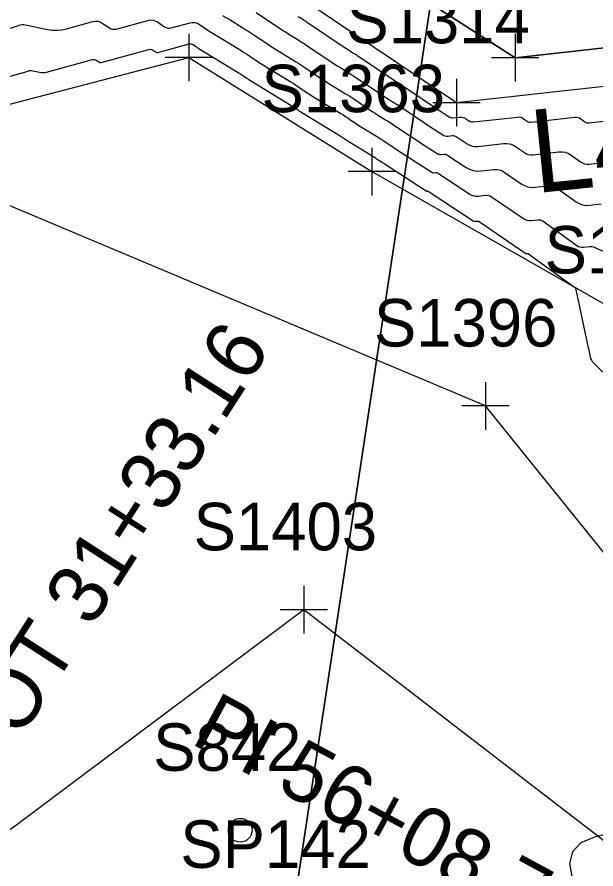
# Model space of a CAD drawing. Extents: x 816928 to 825690, y 436959 to 448212.
# Drawn here: x 818792.7 to 818841.5, y 445120.7 to 445192.4 of the extents above; entities that cross this region are included whole.
import ezdxf

# ---------------------------------------------------------------- set-up
doc = ezdxf.new("R2010")
doc.units = 0
for name, color, linetype in [('SURVEY - CENTERLINE - Preliminary Curve Text', 7, 'Continuous'), ('SURVEY - CONTOURS - Index with Text', 7, 'Continuous'), ('SURVEY - CONTOURS - Intermediate with optional Text', 7, 'Continuous'), ('SURVEY - DRAINAGE - Bridge Hydraulic Data - Points - Locators', 7, 'Continuous'), ('SURVEY - DRAINAGE - Bridge Hydraulic Data - Points - Numbers', 7, 'Continuous'), ('SURVEY - DRAINAGE - Bridge Hydraulic Data with Text', 7, 'Continuous'), ('SURVEY - DRAINAGE - Natural Features', 7, 'Continuous'), ('SURVEY - DRAINAGE - Natural Features - Points - Locators', 7, 'Continuous'), ('SURVEY - DTM - Spot Points - Locators', 7, 'Continuous'), ('SURVEY - DTM - Spot Points - Point Numbers', 7, 'Continuous'), ('SURVEY - NON-TRANSPORTATION - Features', 7, 'Continuous'), ('SURVEY - NON-TRANSPORTATION - Features - Points - Locators', 7, 'Continuous'), ('SURVEY - NON-TRANSPORTATION - Features - Points - Numbers', 7, 'Continuous'), ('SURVEY - PROPERTY - Parcels', 7, 'Continuous'), ('SURVEY - PROPERTY - Property Lines', 7, 'Continuous'), ('SURVEY - PROPERTY - Property Lines - Points - Numbers', 7, 'Continuous'), ('SURVEY - VEGETATION - Features - Points - Locators', 7, 'Continuous'), ('SURVEY - VEGETATION - Features - Points - Numbers', 7, 'Continuous'), ('SURVEY - VEGETATION - Features with Text', 7, 'Continuous')]:
    doc.layers.add(name, color=color, linetype=linetype)

msp = doc.modelspace()

# ---------------------------------------------------------------- linework, layer by layer
at = {"layer": 'SURVEY - CONTOURS - Index with Text'}
msp.add_lwpolyline([(818816.387, 445192.468), (818816.485, 445192.406), (818816.583, 445192.345), (818816.903, 445192.149), (818816.972, 445192.106), (818817.04, 445192.063), (818817.108, 445192.019), (818817.175, 445191.974), (818820.363, 445189.832), (818820.459, 445189.768), (818820.555, 445189.706), (818820.652, 445189.644), (818820.75, 445189.584), (818821.069, 445189.387), (818821.138, 445189.345), (818821.206, 445189.302), (818821.273, 445189.258), (818821.34, 445189.214), (818824.601, 445187.022), (818824.662, 445186.982), (818824.723, 445186.942), (818824.784, 445186.904), (818824.845, 445186.865), (818825.047, 445186.742), (818825.09, 445186.715), (818825.133, 445186.688), (818825.176, 445186.66), (818825.218, 445186.632), (818828.458, 445184.454), (818828.554, 445184.39), (818828.651, 445184.326), (818828.747, 445184.263), (818828.844, 445184.2), (818829.161, 445183.994), (818829.231, 445183.957), (818829.304, 445183.933), (818829.379, 445183.922), (818829.458, 445183.924), (818830.057, 445183.991), (818830.176, 445183.994), (818830.291, 445183.978), (818830.401, 445183.941), (818830.506, 445183.883), (818830.842, 445183.664), (818830.916, 445183.624), (818830.993, 445183.598), (818831.073, 445183.586), (818831.157, 445183.588), (818834.893, 445184.006), (818835.017, 445184.009), (818835.136, 445183.991), (818835.25, 445183.951), (818835.358, 445183.889), (818835.703, 445183.652), (818835.778, 445183.609), (818835.858, 445183.581), (818835.941, 445183.569), (818836.028, 445183.571), (818839.719, 445183.984), (818839.849, 445183.988), (818839.973, 445183.968), (818840.09, 445183.924), (818840.202, 445183.858), (818840.556, 445183.603), (818840.634, 445183.556), (818840.716, 445183.526), (818840.802, 445183.512), (818840.893, 445183.514), (818843.638, 445183.823)], dxfattribs=at)
at = {"layer": 'SURVEY - CONTOURS - Intermediate with optional Text'}
for points in [[(818792.146, 445191.492), (818792.828, 445191.723), (818792.975, 445191.763), (818793.123, 445191.782), (818793.272, 445191.782), (818793.423, 445191.761), (818795.293, 445191.381), (818795.693, 445191.323), (818796.091, 445191.312), (818796.488, 445191.349), (818796.884, 445191.433), (818799.098, 445192.038), (818799.307, 445192.074), (818799.51, 445192.064), (818799.704, 445192.009), (818799.891, 445191.908), (818800.491, 445191.505), (818800.622, 445191.435), (818800.759, 445191.396), (818800.9, 445191.389), (818801.047, 445191.413), (818803.732, 445192.139), (818803.944, 445192.174), (818804.148, 445192.164), (818804.345, 445192.108), (818804.534, 445192.006), (818805.139, 445191.6), (818805.271, 445191.529), (818805.408, 445191.489), (818805.551, 445191.482), (818805.7, 445191.506), (818807.286, 445191.93), (818807.499, 445191.965), (818807.704, 445191.954), (818807.902, 445191.898), (818808.092, 445191.796), (818808.701, 445191.387), (818808.831, 445191.3), (818808.963, 445191.214), (818809.096, 445191.13), (818809.229, 445191.047), (818811.554, 445189.622), (818811.746, 445189.503), (818811.937, 445189.381), (818812.127, 445189.258), (818812.316, 445189.133), (818812.93, 445188.72), (818813.062, 445188.632), (818813.194, 445188.546), (818813.328, 445188.461), (818813.463, 445188.378), (818815.771, 445186.962), (818815.965, 445186.842), (818816.157, 445186.719), (818816.349, 445186.595), (818816.539, 445186.469), (818817.158, 445186.053), (818817.291, 445185.964), (818817.425, 445185.877), (818817.56, 445185.792), (818817.696, 445185.707), (818819.987, 445184.302), (818820.182, 445184.18), (818820.377, 445184.057), (818820.57, 445183.931), (818820.761, 445183.804), (818821.386, 445183.385), (818821.52, 445183.295), (818821.655, 445183.208), (818821.791, 445183.121), (818821.928, 445183.036), (818823.124, 445182.302), (818823.321, 445182.18), (818823.516, 445182.056), (818823.71, 445181.93), (818823.903, 445181.802), (818824.531, 445181.38), (818824.665, 445181.29), (818824.8, 445181.2), (818824.936, 445181.112), (818825.071, 445181.023), (818827.645, 445179.357), (818827.689, 445179.333), (818827.735, 445179.318), (818827.783, 445179.311), (818827.833, 445179.312), (818827.999, 445179.331), (818828.034, 445179.332), (818828.068, 445179.327), (818828.1, 445179.316), (818828.131, 445179.3), (818830.849, 445177.519), (818831.016, 445177.428), (818831.192, 445177.37), (818831.374, 445177.343), (818831.565, 445177.349), (818832.199, 445177.419), (818832.332, 445177.423), (818832.459, 445177.403), (818832.581, 445177.361), (818832.697, 445177.295), (818835.378, 445175.453), (818835.527, 445175.369), (818835.682, 445175.314), (818835.846, 445175.289), (818836.016, 445175.294), (818836.586, 445175.358), (818836.706, 445175.361), (818836.819, 445175.342), (818836.927, 445175.302), (818837.03, 445175.241), (818839.873, 445173.19), (818840.002, 445173.113), (818840.137, 445173.063), (818840.28, 445173.04), (818840.429, 445173.044), (818840.93, 445173.1), (818841.036, 445173.106), (818841.14, 445173.097), (818841.242, 445173.074), (818841.342, 445173.038), (818843.473, 445172.104)], [(818810.05, 445192.555), (818810.308, 445192.392), (818810.567, 445192.231), (818811.746, 445191.508), (818811.998, 445191.352), (818812.248, 445191.193), (818812.497, 445191.032), (818812.744, 445190.868), (818813.803, 445190.156), (818814.031, 445190.005), (818814.26, 445189.856), (818814.491, 445189.709), (818814.723, 445189.565), (818815.935, 445188.822), (818816.193, 445188.662), (818816.45, 445188.498), (818816.705, 445188.333), (818816.959, 445188.164), (818818.014, 445187.455), (818818.241, 445187.304), (818818.47, 445187.156), (818818.7, 445187.01), (818818.931, 445186.866), (818820.138, 445186.126), (818820.396, 445185.966), (818820.652, 445185.803), (818820.906, 445185.638), (818821.159, 445185.47), (818822.273, 445184.721), (818822.475, 445184.587), (818822.679, 445184.454), (818822.884, 445184.324), (818823.09, 445184.196), (818823.767, 445183.781), (818823.912, 445183.691), (818824.055, 445183.6), (818824.198, 445183.507), (818824.34, 445183.413), (818825.56, 445182.593), (818825.822, 445182.418), (818826.085, 445182.244), (818826.348, 445182.071), (818826.612, 445181.899), (818828.111, 445180.928), (818828.183, 445180.889), (818828.259, 445180.864), (818828.339, 445180.852), (818828.421, 445180.855), (818828.696, 445180.885), (818828.754, 445180.887), (818828.809, 445180.879), (818828.862, 445180.861), (818828.913, 445180.834), (818830.544, 445179.765), (818830.835, 445179.607), (818831.139, 445179.505), (818831.457, 445179.459), (818831.788, 445179.469), (818832.89, 445179.592), (818833.122, 445179.598), (818833.343, 445179.564), (818833.554, 445179.49), (818833.755, 445179.375), (818835.193, 445178.388), (818835.467, 445178.232), (818835.756, 445178.13), (818836.058, 445178.084), (818836.374, 445178.093), (818837.43, 445178.211), (818837.651, 445178.216), (818837.861, 445178.182), (818838.061, 445178.108), (818838.251, 445177.995), (818839.816, 445176.866), (818840.074, 445176.712), (818840.346, 445176.612), (818840.632, 445176.566), (818840.933, 445176.573), (818841.937, 445176.686)], [(818812.856, 445192.815), (818814.905, 445191.438), (818815.114, 445191.299), (818815.324, 445191.163), (818815.536, 445191.028), (818815.749, 445190.896), (818816.448, 445190.468), (818816.597, 445190.375), (818816.745, 445190.281), (818816.893, 445190.185), (818817.039, 445190.088), (818819.096, 445188.706), (818819.304, 445188.568), (818819.513, 445188.432), (818819.724, 445188.298), (818819.937, 445188.166), (818820.632, 445187.739), (818820.781, 445187.647), (818820.929, 445187.553), (818821.075, 445187.458), (818821.221, 445187.361), (818823.437, 445185.872), (818823.568, 445185.784), (818823.701, 445185.698), (818823.834, 445185.614), (818823.968, 445185.531), (818824.407, 445185.261), (818824.501, 445185.203), (818824.594, 445185.144), (818824.687, 445185.083), (818824.779, 445185.022), (818826.949, 445183.564), (818827.158, 445183.424), (818827.368, 445183.285), (818827.578, 445183.147), (818827.789, 445183.01), (818828.577, 445182.5), (818828.678, 445182.445), (818828.784, 445182.41), (818828.895, 445182.394), (818829.01, 445182.397), (818829.393, 445182.44), (818829.474, 445182.442), (818829.551, 445182.431), (818829.625, 445182.406), (818829.696, 445182.368), (818830.643, 445181.747), (818830.851, 445181.634), (818831.068, 445181.561), (818831.295, 445181.528), (818831.532, 445181.535), (818833.7, 445181.777), (818833.972, 445181.785), (818834.231, 445181.745), (818834.479, 445181.658), (818834.715, 445181.523), (818835.467, 445181.007), (818835.632, 445180.913), (818835.806, 445180.852), (818835.988, 445180.824), (818836.178, 445180.829), (818838.353, 445181.073), (818838.637, 445181.08), (818838.907, 445181.036), (818839.164, 445180.942), (818839.407, 445180.796), (818840.181, 445180.238), (818840.352, 445180.136), (818840.531, 445180.07), (818840.721, 445180.039), (818840.919, 445180.044), (818842.789, 445180.255)], [(818789.092, 445186.596), (818793.125, 445187.713), (818793.204, 445187.735), (818793.282, 445187.758), (818793.36, 445187.783), (818793.437, 445187.809), (818793.69, 445187.894), (818793.745, 445187.909), (818793.799, 445187.916), (818793.855, 445187.916), (818793.911, 445187.908), (818794.604, 445187.767), (818794.752, 445187.746), (818794.9, 445187.742), (818795.047, 445187.756), (818795.193, 445187.787), (818799.06, 445188.843), (818799.139, 445188.857), (818799.216, 445188.853), (818799.29, 445188.832), (818799.361, 445188.794), (818799.588, 445188.642), (818799.637, 445188.615), (818799.689, 445188.6), (818799.743, 445188.598), (818799.798, 445188.607), (818803.821, 445189.694), (818803.903, 445189.707), (818803.981, 445189.703), (818804.057, 445189.682), (818804.13, 445189.643), (818804.364, 445189.485), (818804.415, 445189.458), (818804.469, 445189.443), (818804.524, 445189.44), (818804.581, 445189.449), (818807.219, 445190.154), (818807.303, 445190.168), (818807.383, 445190.164), (818807.461, 445190.141), (818807.535, 445190.101), (818807.774, 445189.941), (818807.825, 445189.907), (818807.877, 445189.873), (818807.929, 445189.84), (818807.981, 445189.808), (818811.474, 445187.666), (818811.551, 445187.619), (818811.627, 445187.57), (818811.703, 445187.521), (818811.778, 445187.471), (818812.023, 445187.306), (818812.076, 445187.271), (818812.129, 445187.237), (818812.182, 445187.203), (818812.236, 445187.17), (818815.708, 445185.04), (818815.787, 445184.991), (818815.865, 445184.942), (818815.943, 445184.891), (818816.02, 445184.84), (818816.272, 445184.671), (818816.326, 445184.635), (818816.38, 445184.599), (818816.435, 445184.564), (818816.49, 445184.53), (818819.941, 445182.413), (818820.022, 445182.363), (818820.103, 445182.312), (818820.182, 445182.26), (818820.262, 445182.207), (818820.52, 445182.034), (818820.575, 445181.997), (818820.631, 445181.961), (818820.687, 445181.925), (818820.744, 445181.89), (818822.816, 445180.618), (818822.898, 445180.567), (818822.98, 445180.515), (818823.061, 445180.463), (818823.141, 445180.409), (818823.404, 445180.233), (818823.46, 445180.195), (818823.516, 445180.158), (818823.573, 445180.121), (818823.63, 445180.084), (818827.178, 445177.785), (818827.194, 445177.777), (818827.21, 445177.772), (818827.227, 445177.769), (818827.244, 445177.77), (818827.302, 445177.776), (818827.314, 445177.777), (818827.326, 445177.775), (818827.337, 445177.771), (818827.348, 445177.765), (818831.154, 445175.273), (818831.198, 445175.249), (818831.244, 445175.234), (818831.292, 445175.227), (818831.341, 445175.228), (818831.508, 445175.247), (818831.543, 445175.248), (818831.576, 445175.243), (818831.608, 445175.232), (818831.638, 445175.214), (818835.564, 445172.519), (818835.586, 445172.506), (818835.609, 445172.498), (818835.633, 445172.494), (818835.658, 445172.495), (818835.743, 445172.505), (818835.76, 445172.505), (818835.777, 445172.502), (818835.793, 445172.496), (818835.808, 445172.487), (818839.687, 445169.689), (818839.716, 445169.664), (818839.74, 445169.635), (818839.757, 445169.602), (818839.768, 445169.565), (818839.795, 445169.439), (818839.801, 445169.412), (818839.807, 445169.385), (818839.812, 445169.358), (818839.818, 445169.33), (818840.666, 445165.356), (818840.711, 445165.143), (818840.757, 445164.93), (818840.802, 445164.717), (818840.848, 445164.504), (818840.996, 445163.808), (818841.038, 445163.664), (818841.098, 445163.531), (818841.178, 445163.408), (818841.277, 445163.296), (818842.818, 445161.782)], [(818847.904, 445125.032), (818841.375, 445123.369), (818840.207, 445122.885), (818839.501, 445122.148), (818839.256, 445121.157), (818839.474, 445119.911)]]:
    msp.add_lwpolyline(points, dxfattribs=at)
at = {"layer": 'SURVEY - DRAINAGE - Bridge Hydraulic Data - Points - Locators'}
for p, q in [((818807.177, 445191.01), (818807.177, 445187.01)), ((818809.177, 445189.01), (818805.177, 445189.01)), ((818829.741, 445187.211), (818829.741, 445183.211)), ((818831.741, 445185.211), (818827.741, 445185.211)), ((818822.594, 445181.409), (818822.594, 445177.409)), ((818824.594, 445179.409), (818820.594, 445179.409))]:
    msp.add_line(p, q, dxfattribs=at)
at = {"layer": 'SURVEY - DRAINAGE - Bridge Hydraulic Data with Text'}
for p, q in [((818798.356, 445212.301), (818834.683, 445188.997)), ((818834.683, 445188.997), (818885.355, 445194.671))]:
    msp.add_line(p, q, dxfattribs=at)
for points in [[(818975.535, 445161.489), (818974.654, 445162.222), (818955.542, 445179.169), (818885.6, 445191.376), (818829.741, 445185.211), (818795.23, 445208.399), (818755.569, 445194.059), (818710.632, 445195.982)], [(818784.519, 445183.127), (818807.177, 445189.01), (818822.594, 445179.409), (818846.448, 445165.831), (818864.623, 445142.909), (818851.635, 445125.23), (818852.677, 445121.979), (818854.948, 445121.819)]]:
    msp.add_lwpolyline(points, dxfattribs=at)
at = {"layer": 'SURVEY - DRAINAGE - Natural Features'}
msp.add_lwpolyline([(818976.92, 445167.021), (818959.968, 445184.233), (818885.355, 445194.671), (818834.683, 445188.997), (818798.356, 445212.301), (818757.037, 445198.917), (818710.514, 445201.057)], dxfattribs=at)
at = {"layer": 'SURVEY - DRAINAGE - Natural Features - Points - Locators'}
for p, q in [((818834.683, 445190.997), (818834.683, 445186.997)), ((818836.683, 445188.997), (818832.683, 445188.997))]:
    msp.add_line(p, q, dxfattribs=at)
at = {"layer": 'SURVEY - DTM - Spot Points - Locators'}
msp.add_circle((818811.511, 445123.955), 1, dxfattribs=at)
at = {"layer": 'SURVEY - NON-TRANSPORTATION - Features'}
msp.add_lwpolyline([(818878.723, 445102.028), (818832.174, 445159.68), (818783.535, 445180.107), (818767.737, 445165.919), (818720.129, 445113.759)], dxfattribs=at)
at = {"layer": 'SURVEY - NON-TRANSPORTATION - Features - Points - Locators'}
for p, q in [((818832.174, 445161.68), (818832.174, 445157.68)), ((818834.174, 445159.68), (818830.174, 445159.68))]:
    msp.add_line(p, q, dxfattribs=at)
at = {"layer": 'SURVEY - PROPERTY - Parcels'}
for p, q in [((818881.306, 445547.674), (818780.722, 444885.014)), ((818815.75, 445115.787), (818881.306, 445547.674))]:
    msp.add_line(p, q, dxfattribs=at)
at = {"layer": 'SURVEY - PROPERTY - Property Lines'}
msp.add_line((818881.306, 445547.674), (818780.722, 444885.014), dxfattribs=at)
at = {"layer": 'SURVEY - VEGETATION - Features - Points - Locators'}
for p, q in [((818816.87, 445144.523), (818816.87, 445140.523)), ((818818.87, 445142.523), (818814.87, 445142.523))]:
    msp.add_line(p, q, dxfattribs=at)
at = {"layer": 'SURVEY - VEGETATION - Features with Text'}
msp.add_lwpolyline([(818875.35, 445097.529), (818816.87, 445142.523), (818782.15, 445116.559), (818758.749, 445085.99), (818745.74, 445051.115), (818754.139, 445016.546)], dxfattribs=at)

# ---------------------------------------------------------------- texts
at = {"layer": 'SURVEY - CENTERLINE - Preliminary Curve Text'}
msp.add_text('PI 56+08.71', height=5, rotation=331.66346, dxfattribs=at).set_placement((818807.226, 445131.319))
at = {"layer": 'SURVEY - DRAINAGE - Bridge Hydraulic Data - Points - Numbers'}
for s, p in [('S1314', (818820.453, 445190.211)), ('S1363', (818813.306, 445184.409)), ('S1364', (818837.16, 445170.831))]:
    msp.add_text(s, height=4, dxfattribs=at).set_placement(p)
at = {"layer": 'SURVEY - DRAINAGE - Bridge Hydraulic Data with Text'}
for s, height, rotation, p in [('L4', 7, 5.92367, (818836.366, 445177.584)), ('POT 31+33.16', 5, 57.31991, (818790.546, 445127.781))]:
    msp.add_text(s, height=height, rotation=rotation, dxfattribs=at).set_placement(p)
at = {"layer": 'SURVEY - DTM - Spot Points - Point Numbers'}
msp.add_text('S842', height=4, dxfattribs=at).set_placement((818804.175, 445128.955))
at = {"layer": 'SURVEY - NON-TRANSPORTATION - Features - Points - Numbers'}
msp.add_text('S1396', height=4, dxfattribs=at).set_placement((818822.776, 445164.68))
at = {"layer": 'SURVEY - PROPERTY - Property Lines - Points - Numbers'}
msp.add_text('SP142', height=4, dxfattribs=at).set_placement((818806.463, 445120.787))
at = {"layer": 'SURVEY - VEGETATION - Features - Points - Numbers'}
msp.add_text('S1403', height=4, dxfattribs=at).set_placement((818807.582, 445147.523))

doc.saveas('drawing.dxf')
